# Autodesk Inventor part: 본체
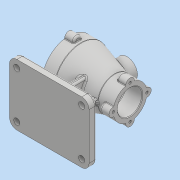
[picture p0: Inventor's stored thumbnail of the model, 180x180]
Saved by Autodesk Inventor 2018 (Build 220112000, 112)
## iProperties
Created: 2020-12
Part Number: 본체
Material: 일반
Document SubType Name: Modeling
Designer: home
Density: 1 g/cm^3
Appearance: 기본값
Mass: 381.528 g
Surface Area: 850.653 cm^2
Volume: 381.528 cm^3
Author: home
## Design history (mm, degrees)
sketch "스케치1"
  geometry: L1 (53, -50)-(-53, -50); L2 (-65, -38)-(-65, 38); L3 (-53, 50)-(53, 50); L4 (65, 38)-(65, -38); C1 r 5 at (53, -38); C2 r 5 at (53, 38); C3 r 5 at (-53, 38); C4 r 5 at (-53, -38); A1 r 12 centre (53, -38) between (53, -50) and (65, -38); A2 r 12 centre (53, 38) between (65, 38) and (53, 50); A3 r 12 centre (-53, 38) between (-53, 50) and (-65, 38); A4 r 12 centre (-53, -38) between (-65, -38) and (-53, -50); 4 further points
  constraints: 8 centre point, 8 end point, 8 point on circle, 8 tangent, 6 point on line, 4 coincident, 3 equal radius, 2 parallel, 1 horizontal, 1 perpendicular
  dimensions: "d0" = 130 distance of point (65, -50) point (-65, -50); "d1" = 100 distance of point (-65, -50) point (-65, 50); "d2" = 65 distance from line of L2 point (0, 0); "d3" = 50 distance from line of point (0, 0) L1; "d4" = 12 radius of A1; "d5" = 10 diameter of C1; "d6" = 10 diameter of C2; "d7" = 10 diameter of C3; "d8" = 10 diameter of C4
extrude "돌출1" new body sketch "스케치1" distance "d9" = 12; taper "d10" = 0 deg
sketch "스케치2"
  geometry: L1 (-70.943, 82)-(67.415, 82); L2 (58, 0)-(48, 0) reference; L3 (50, 103)-(50, 109.5); L4 (50, 109.5)-(25.44, 109.5); L5 (24.578, 109.627)-(-29.578, 125.873); L6 (-30.44, 126)-(-50, 126); L7 (-50, 126)-(-50, 115); L8 (-27, 104.161)-(-27, 108); L9 (-24, 108)-(17, 108); L10 (23, 102)-(49, 102); L11 (-49, 114)-(-30, 114); L12 (-27, 111)-(-27, 111); L13 (20, 105)-(20, 105); L14 (-49, 114)-(-50, 115); L15 (49, 102)-(50, 103); A1 r 3 centre (-30, 111) between (-27, 111) and (-30, 114); A2 r 3 centre (-24, 111) between (-27, 111) and (-24, 108); A3 r 3 centre (17, 105) between (20, 105) and (17, 108); A4 r 3 centre (23, 105) between (20, 105) and (23, 102); A5 r 3 centre (-30.44, 123) between (-29.578, 125.873) and (-30.44, 126); A6 r 3 centre (25.44, 112.5) between (24.578, 109.627) and (25.44, 109.5); 7 further points
  constraints: 28 end point, 14 point on line, 12 point on circle, 12 tangent, 6 centre point, 6 perpendicular, 3 equal radius, 2 vertical, 1 horizontal, 1 parallel
  dimensions: "d11" = 82 distance between parallel lines of L2 L1; "d12" = 88 diameter of L6 L1; "d13" = 55 diameter of L4 L1; "d14" = 20 distance of point (-30, 126) L6.end; "d15" = 100 distance between parallel lines of L3 L7; "d16" = 50 horizontal distance of point (0, 0) L6.end; "d18" = 47 distance of L8.end point (20, 108); "d19" = 23 distance of point (-50, 114) point (-27, 114); "d20" = 64 diameter of L11 L1; "d21" = 52 diameter of L9 L1; "d22" = 40 diameter of L10 L1; "d23" = 3 radius of A1; "d24" = 3 radius of A3 (derived); "d25" = 25 distance of L3.end point (25, 109.5); "d26" = 3 radius of A5 (derived); "d27" = 1 distance of L11.start point (-50, 114); "d28" = 1 distance of L7.end point (-50, 114) (= d27); "d29" = 1 distance of L10.end point (50, 102) (= d27); "d30" = 1 distance of L3.start point (50, 102) (= d29)
revolve "회전1" sketch "스케치2" stored, may be unused: angle "d31" = 90 deg
sketch "스케치5"
  geometry: A1 r 7 centre (0, 27.5) between (6.943, 26.609) and (-6.943, 26.609); A2 r 27.5 centre (0, 0) between (6.943, 26.609) and (-6.943, 26.609); 2 further points
  constraints: 5 point on circle, 2 centre point, 2 vertical alignment, 1 coincident, 1 other
  dimensions: "d47" = 14 diameter of A1
extrude "돌출3" join sketch "스케치5" distance "d48" = 15; taper "d49" = 0 deg
fillet "모깎기3" dims "d57" = 3
fillet "모깎기4" dims "d58" = 1
sketch "스케치7"
  geometry: L1 (-29.578, 38.127)-(24.578, 54.373) reference; L2 (53, 12)-(-53, 12) reference; L3 (-24, 12)-(-24, 39.8); 1 further point
  constraints: 2 end point, 2 point on line, 1 vertical
  dimensions: "d62" = 24 distance from line of point (0, 0) L3
feature "리브1" sketch "스케치7" dims "d63" = 1, "d64" = 8, "d65" = 0, "d66" = 0, "d67" = 1, "d68" = 1
sketch "스케치8"
  geometry: L1 (-29.578, 38.127)-(24.578, 54.373) reference; L2 (53, 12)-(-53, 12) reference; L3 (24, 12)-(24, 54.2); 1 further point
  constraints: 2 end point, 2 point on line, 1 vertical
  dimensions: "d69" = 24 distance from line of point (0, 0) L3
feature "리브2" sketch "스케치8" dims "d70" = 1, "d71" = 8, "d72" = 0, "d73" = 0, "d74" = 1, "d75" = 1
sketch "스케치9"
  geometry: L1 (0, 38)-(0, -38) reference; L2 (0, 38)-(12, 38) reference; L3 (12, -38)-(12, 38) reference; L4 (0, -38)-(12, -38) reference; L5 (12, -38)-(12, 38) reference; L6 (12, 25)-(67.303, 25); L7 (12, -25)-(67.303, -25); A1 r 29 centre (82, 0) between (67.303, 25) and (67.303, -25) reference; 1 further point
  constraints: 4 end point, 2 point on circle, 2 point on line, 1 parallel, 1 perpendicular
  dimensions: "d76" = 50 distance between parallel lines of L6 L7; "d77" = 25 distance from line of point (0, 0) L7
feature "리브3" sketch "스케치9" dims "d78" = 1, "d79" = 8, "d80" = 0, "d81" = 0, "d82" = 1, "d83" = 1
fillet "모깎기5" dims "d84" = 3
node "작업 평면1"
sketch "스케치10"
  geometry: C1 r 17 at (0, 0); 1 further point
  constraints: 1 centre point, 1 coincident
  dimensions: "d87" = 34 diameter of C1
extrude "돌출4" join sketch "스케치10" stored distance "d88" = 15; taper "d89" = 0 deg
sketch "스케치11"
  geometry: 2 further points
  constraints: 1 coincident
hole "구멍3" sketch "스케치11" at (0, 0) diameter "d90" = 22; stored, may be unused: countersink angle "d94" = 90 deg, drill point angle "d96" = 0 deg; dims "d91" = 10, "d92" = 28, "d93" = 1, "d95" = 30
chamfer "모따기1" distance "d97" = 1; stored, may be unused: second distance "d98" = 2, angle "d99" = 45 deg
sketch "스케치12"
  geometry: L1 (-53, -50)-(53, -50) reference; 2 further points
  constraints: 1 vertical alignment, 1 other
  dimensions: "d100" = 10 distance from line of L1 point (0, -40)
feature "엠보싱1" sketch "스케치12" dims "d0" = 130, "d1" = 100, "d2" = 65, "d3" = 50, "d4" = 12, "d5" = 10, "d6" = 10, "d7" = 10, "d8" = 10, "d101" = 0.5, "d102" = 0
fillet "모깎기7" dims "d103" = 3
fillet "모깎기8" dims "d104" = 3
sketch "스케치13"
  geometry: A1 r 7 centre (0, 44) between (6.978, 43.443) and (-6.978, 43.443); A2 r 44 centre (0, 0) between (-6.978, 43.443) and (6.978, 43.443) reference; 1 further point
  constraints: 4 point on circle, 1 centre point
  dimensions: "d105" = 14 diameter of A1; "d106" = 44 distance of A2.centre A1.centre
extrude "돌출5" join sketch "스케치13" distance "d107" = 15; taper "d108" = 0 deg
fillet "모깎기9" dims "d109" = 3
fillet "모깎기10" dims "d110" = 1
sketch "스케치14"
  geometry: A1 r 7 centre (0, 0) between (6.996, 0.249) and (-6.996, 0.249) reference; 2 further points
  constraints: 1 coincident
hole "구멍4" sketch "스케치14" at (0, 0) diameter "d111" = 4.134; stored, may be unused: countersink angle "d115" = 90 deg, drill point angle "d117" = 118 deg; dims "d112" = 9, "d113" = 28, "d114" = 1, "d116" = 11
fillet "모깎기11" dims "d121" = 1
sketch "스케치15"
  geometry: C1 r 20 at (0, -27.5) reference; 2 further points
  constraints: 1 vertical alignment
  dimensions: "d122" = 27.5 distance of C1.centre point (0, 0)
hole "구멍5" sketch "스케치15" at (0, 0) diameter "d123" = 4.134; stored, may be unused: countersink angle "d127" = 90 deg, drill point angle "d129" = 118 deg; dims "d124" = 9, "d125" = 28, "d126" = 1, "d128" = 11
node "솔리드1"
pattern_circular "원형 패턴2" dims angle "d60" = 360 deg
mirror "미러1"
pattern_circular "원형 패턴3" dims "d119" = 360 deg
pattern_circular "원형 패턴4" dims angle "d131" = 360 deg
node "투영된 루프1"
feature "耀䀒"
other parameters: "d86" = 127
